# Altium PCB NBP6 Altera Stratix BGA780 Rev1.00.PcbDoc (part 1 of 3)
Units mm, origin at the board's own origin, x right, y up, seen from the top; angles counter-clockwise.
Board outline 69 x 80.99 mm, 6 copper layers (Top Layer, Upper, lower, VCC_PLANE, GND_PLANE, Bottom Layer); 92 components, 279 nets, 1271 pads, 560 vias.
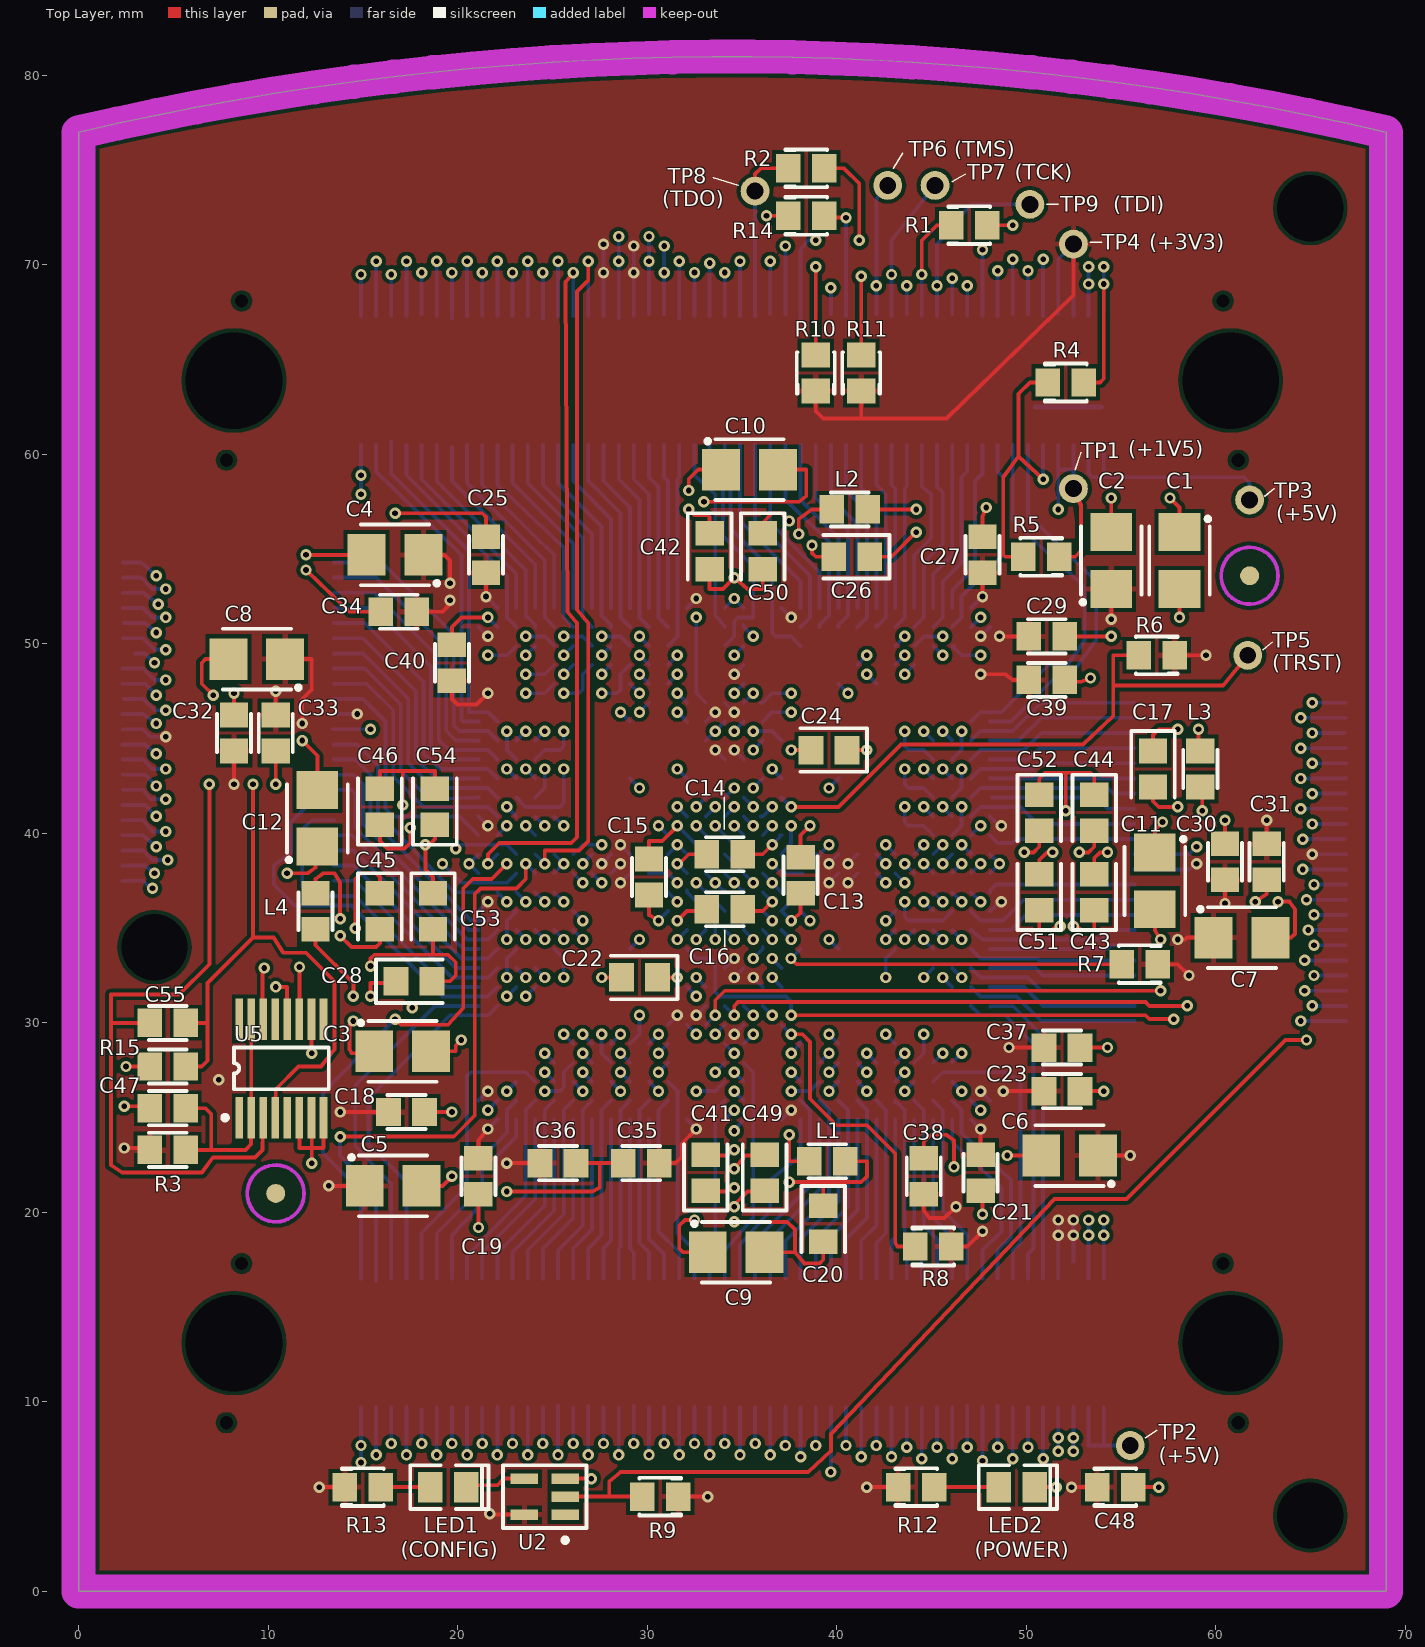
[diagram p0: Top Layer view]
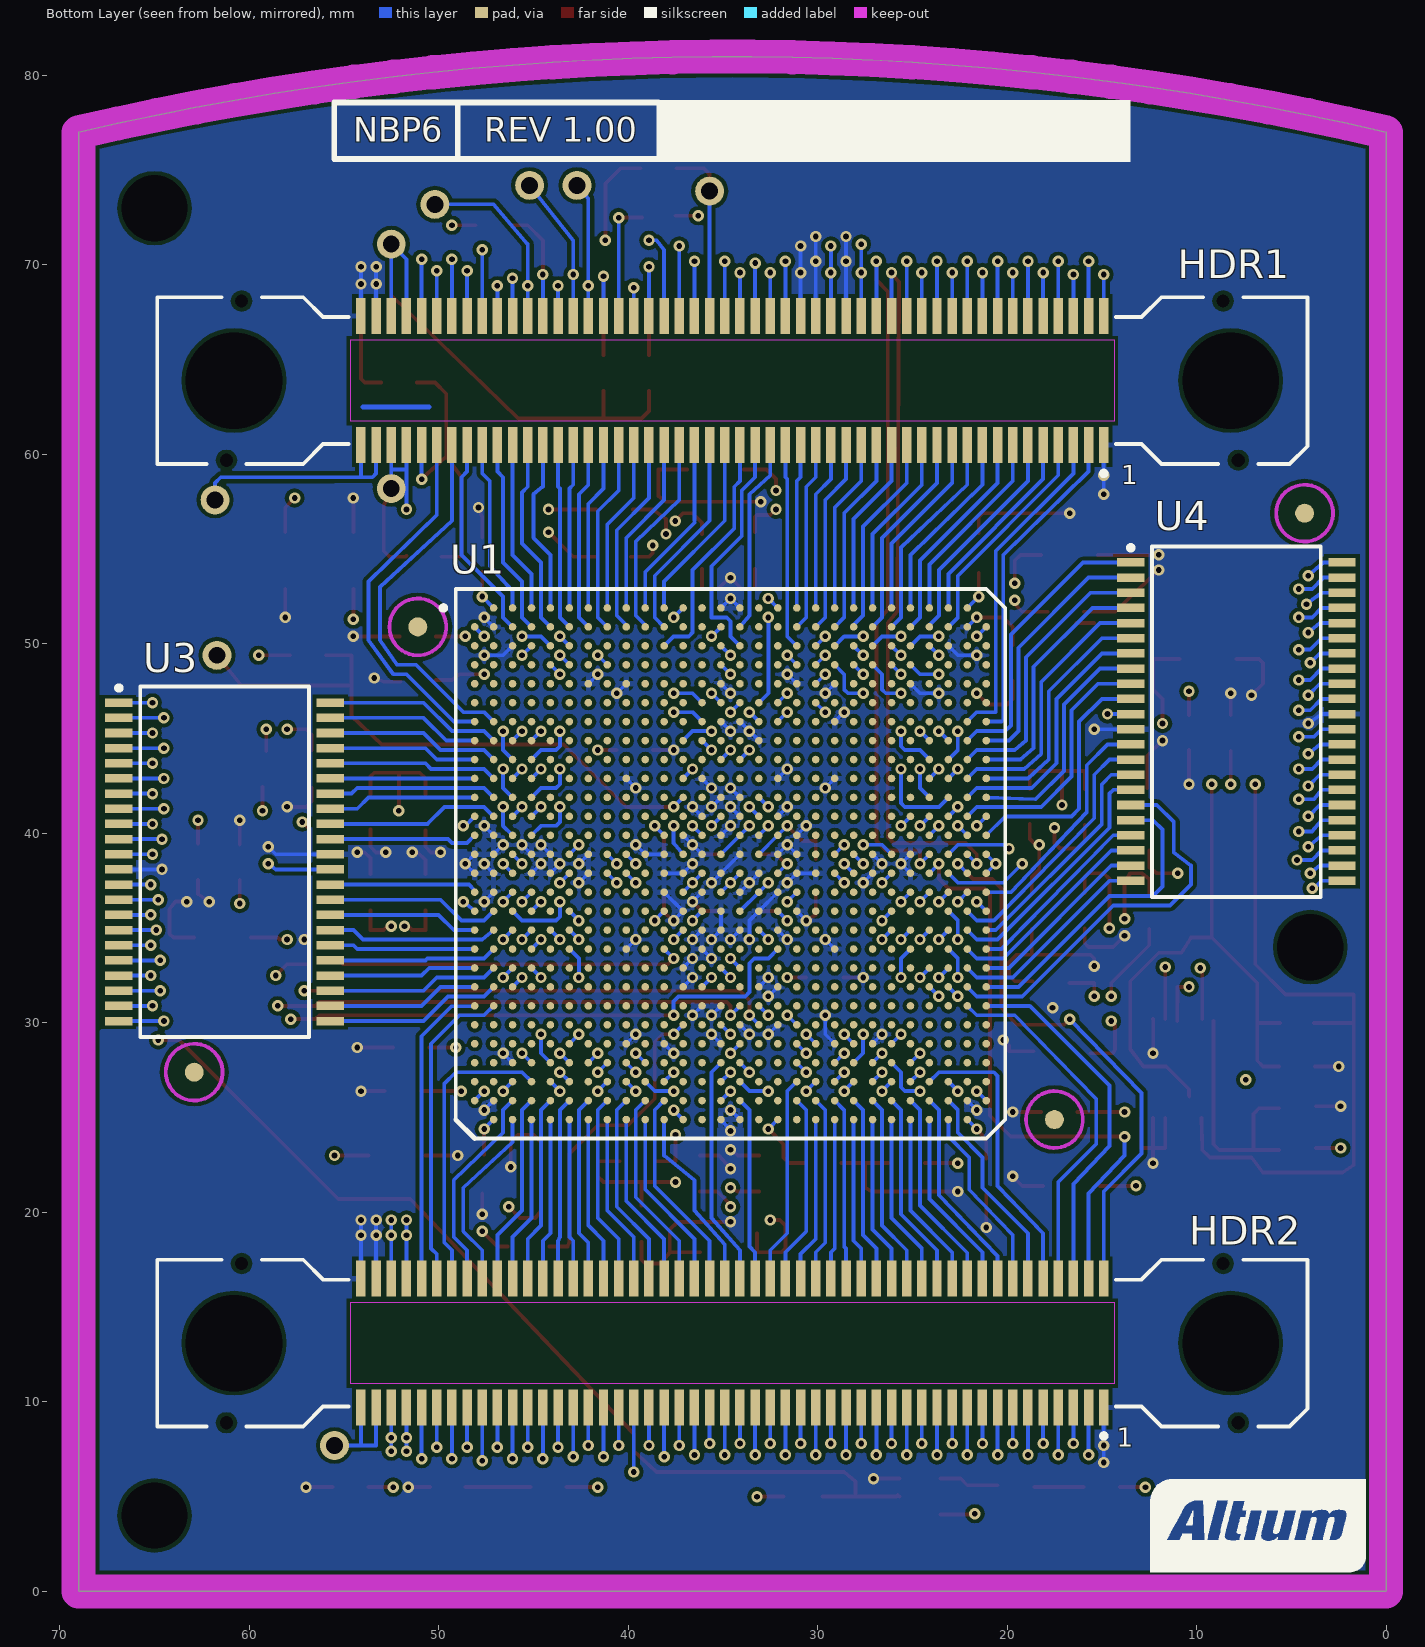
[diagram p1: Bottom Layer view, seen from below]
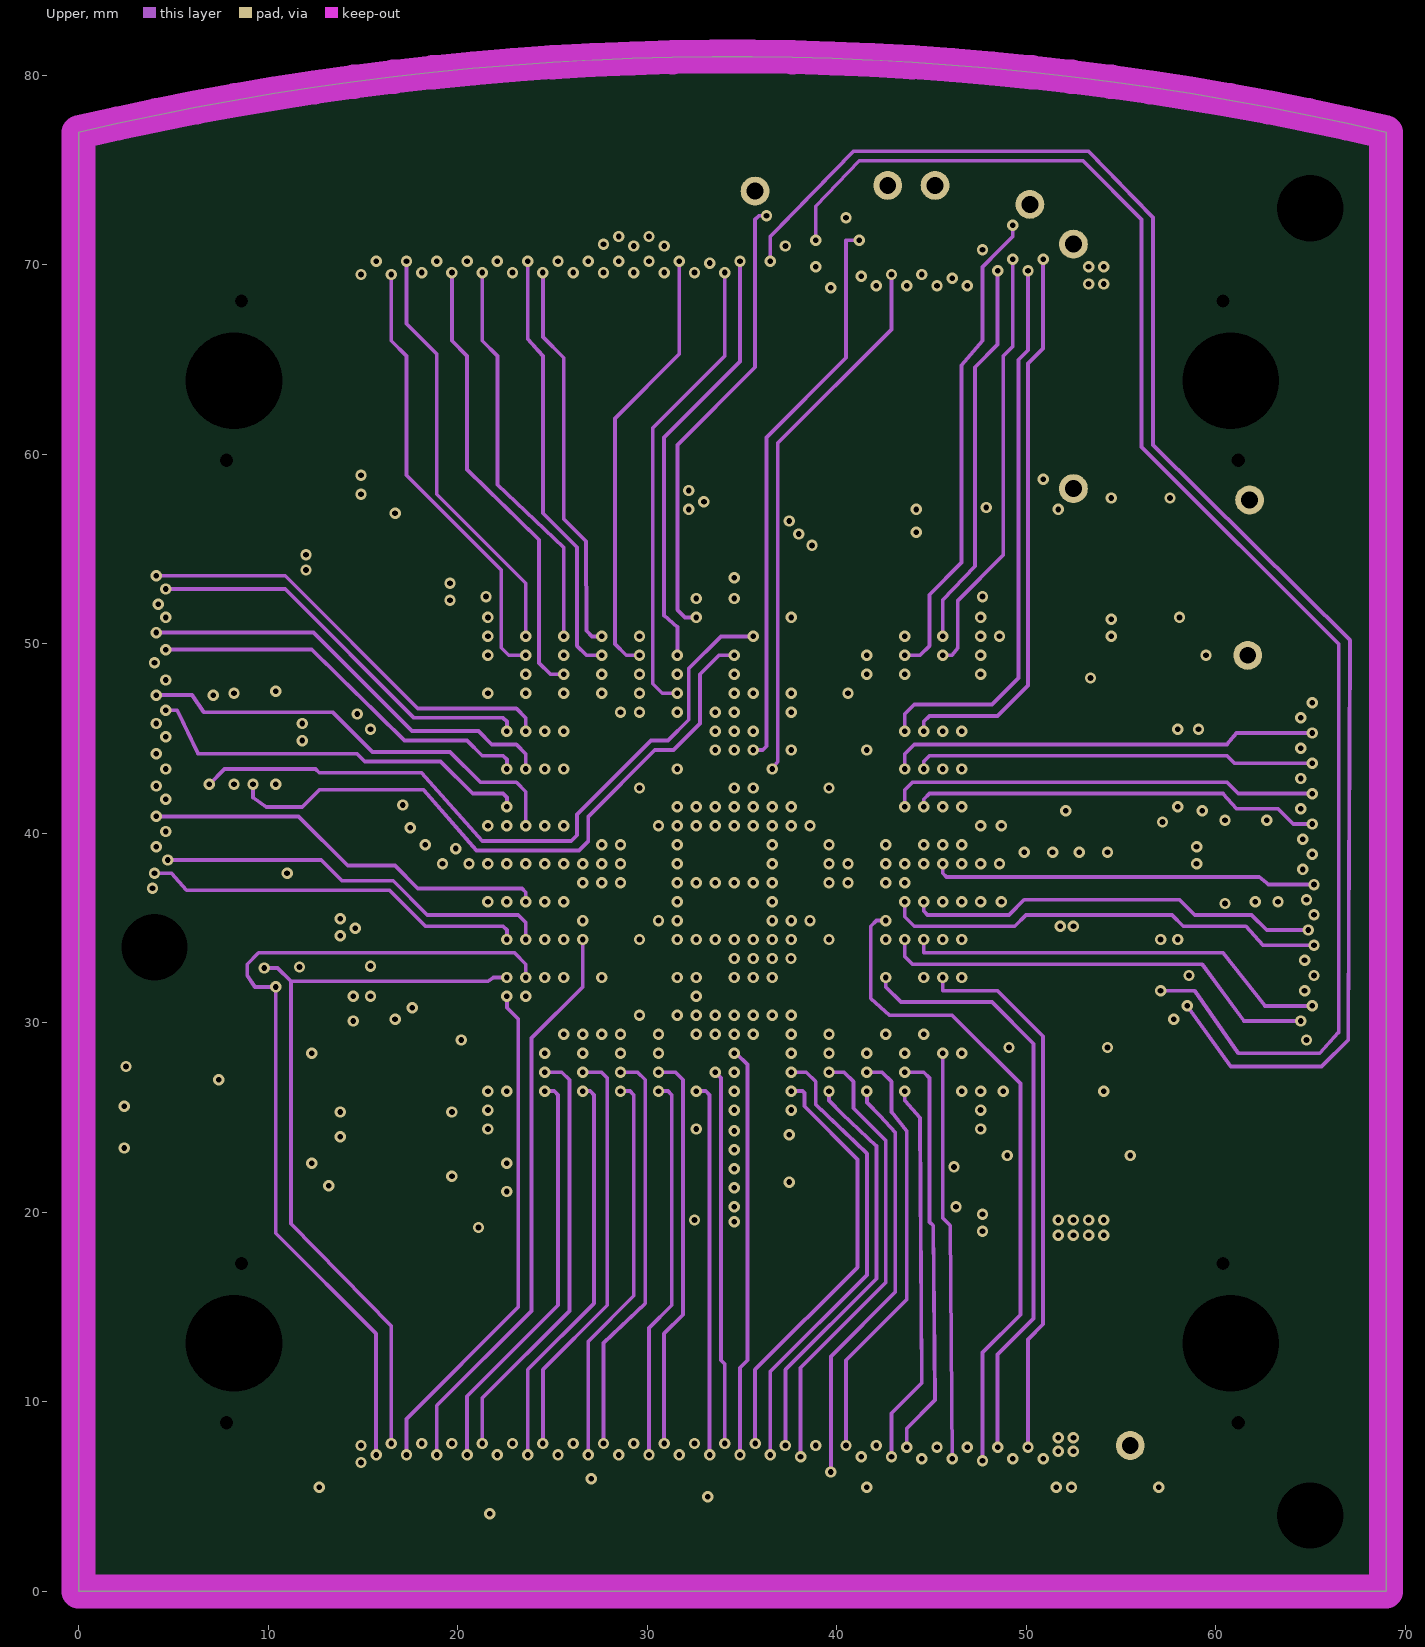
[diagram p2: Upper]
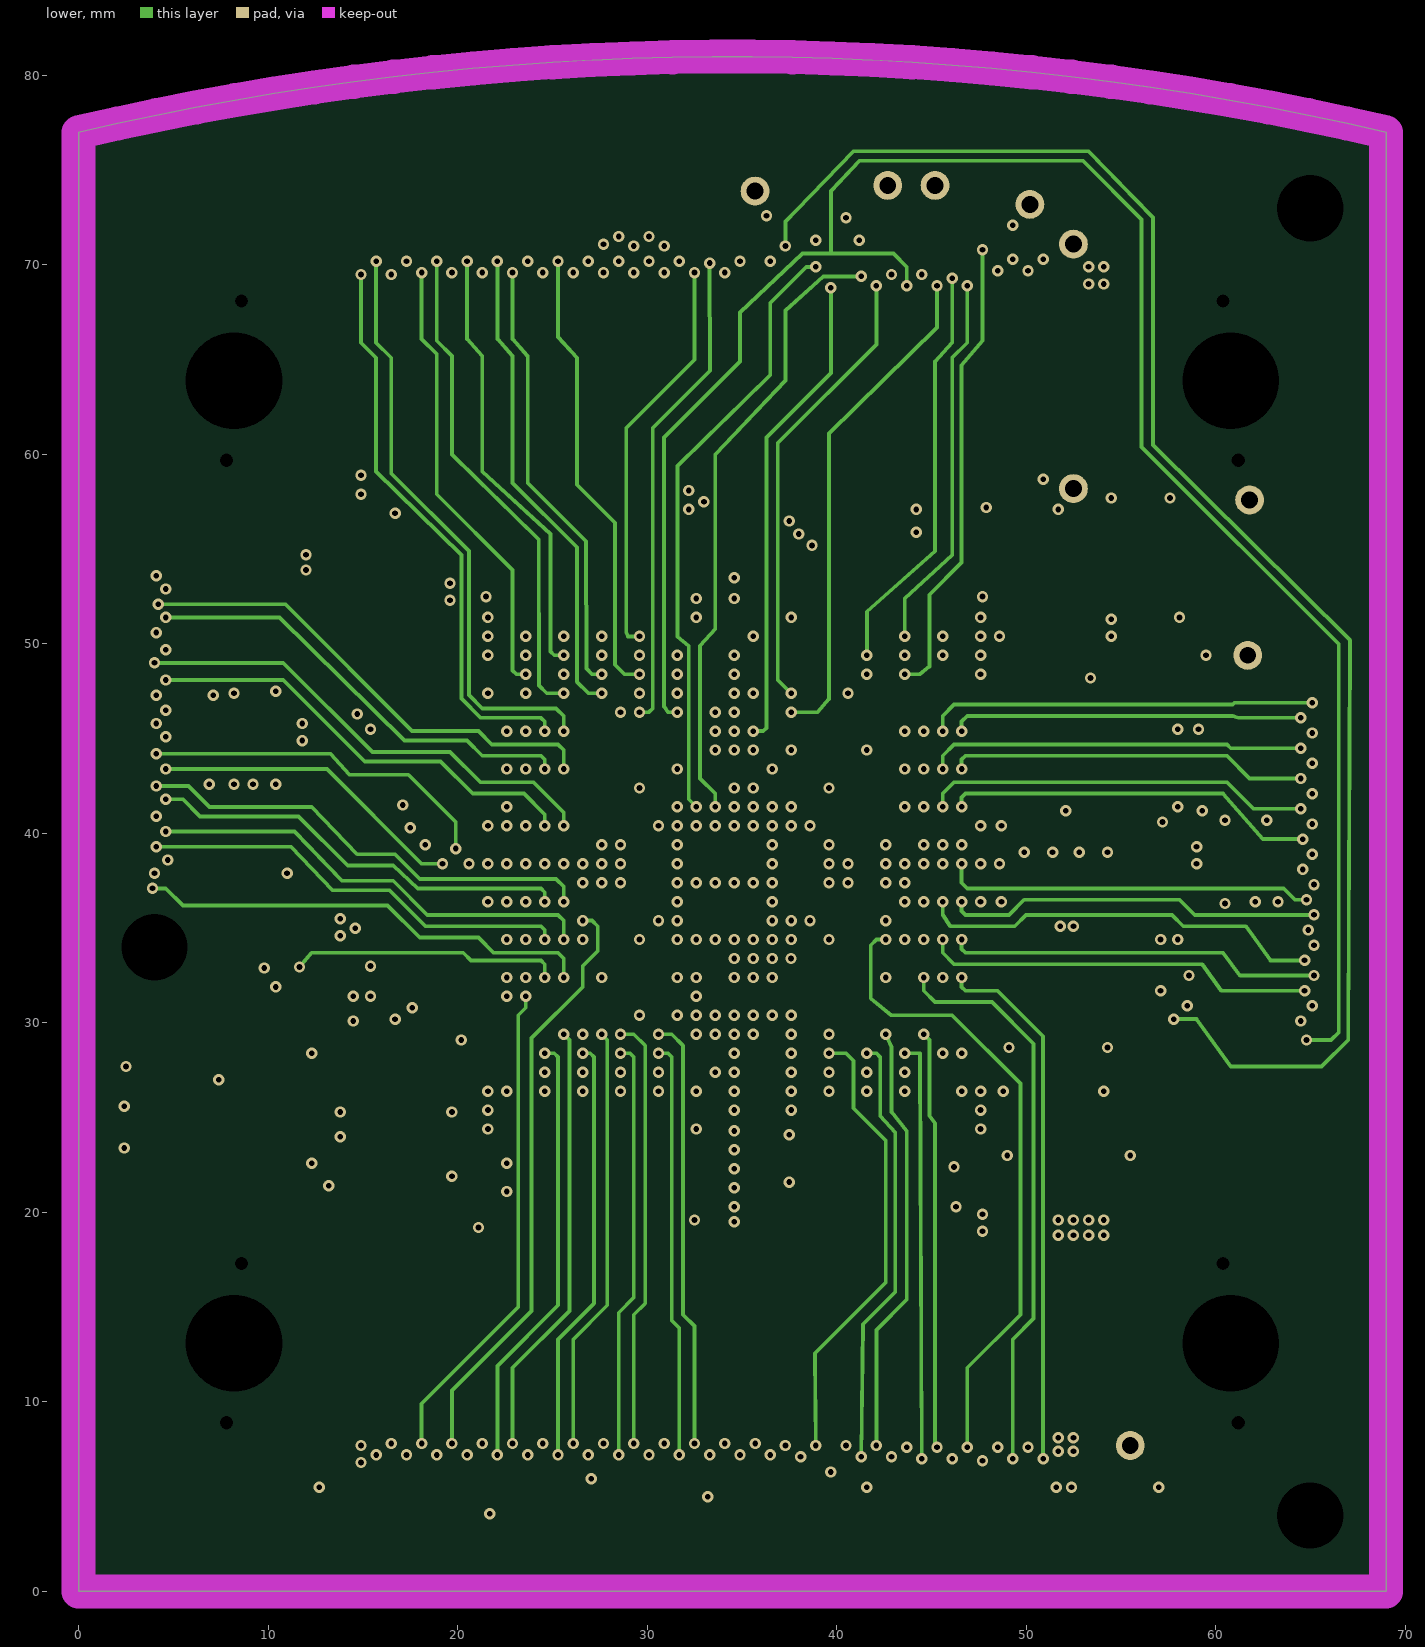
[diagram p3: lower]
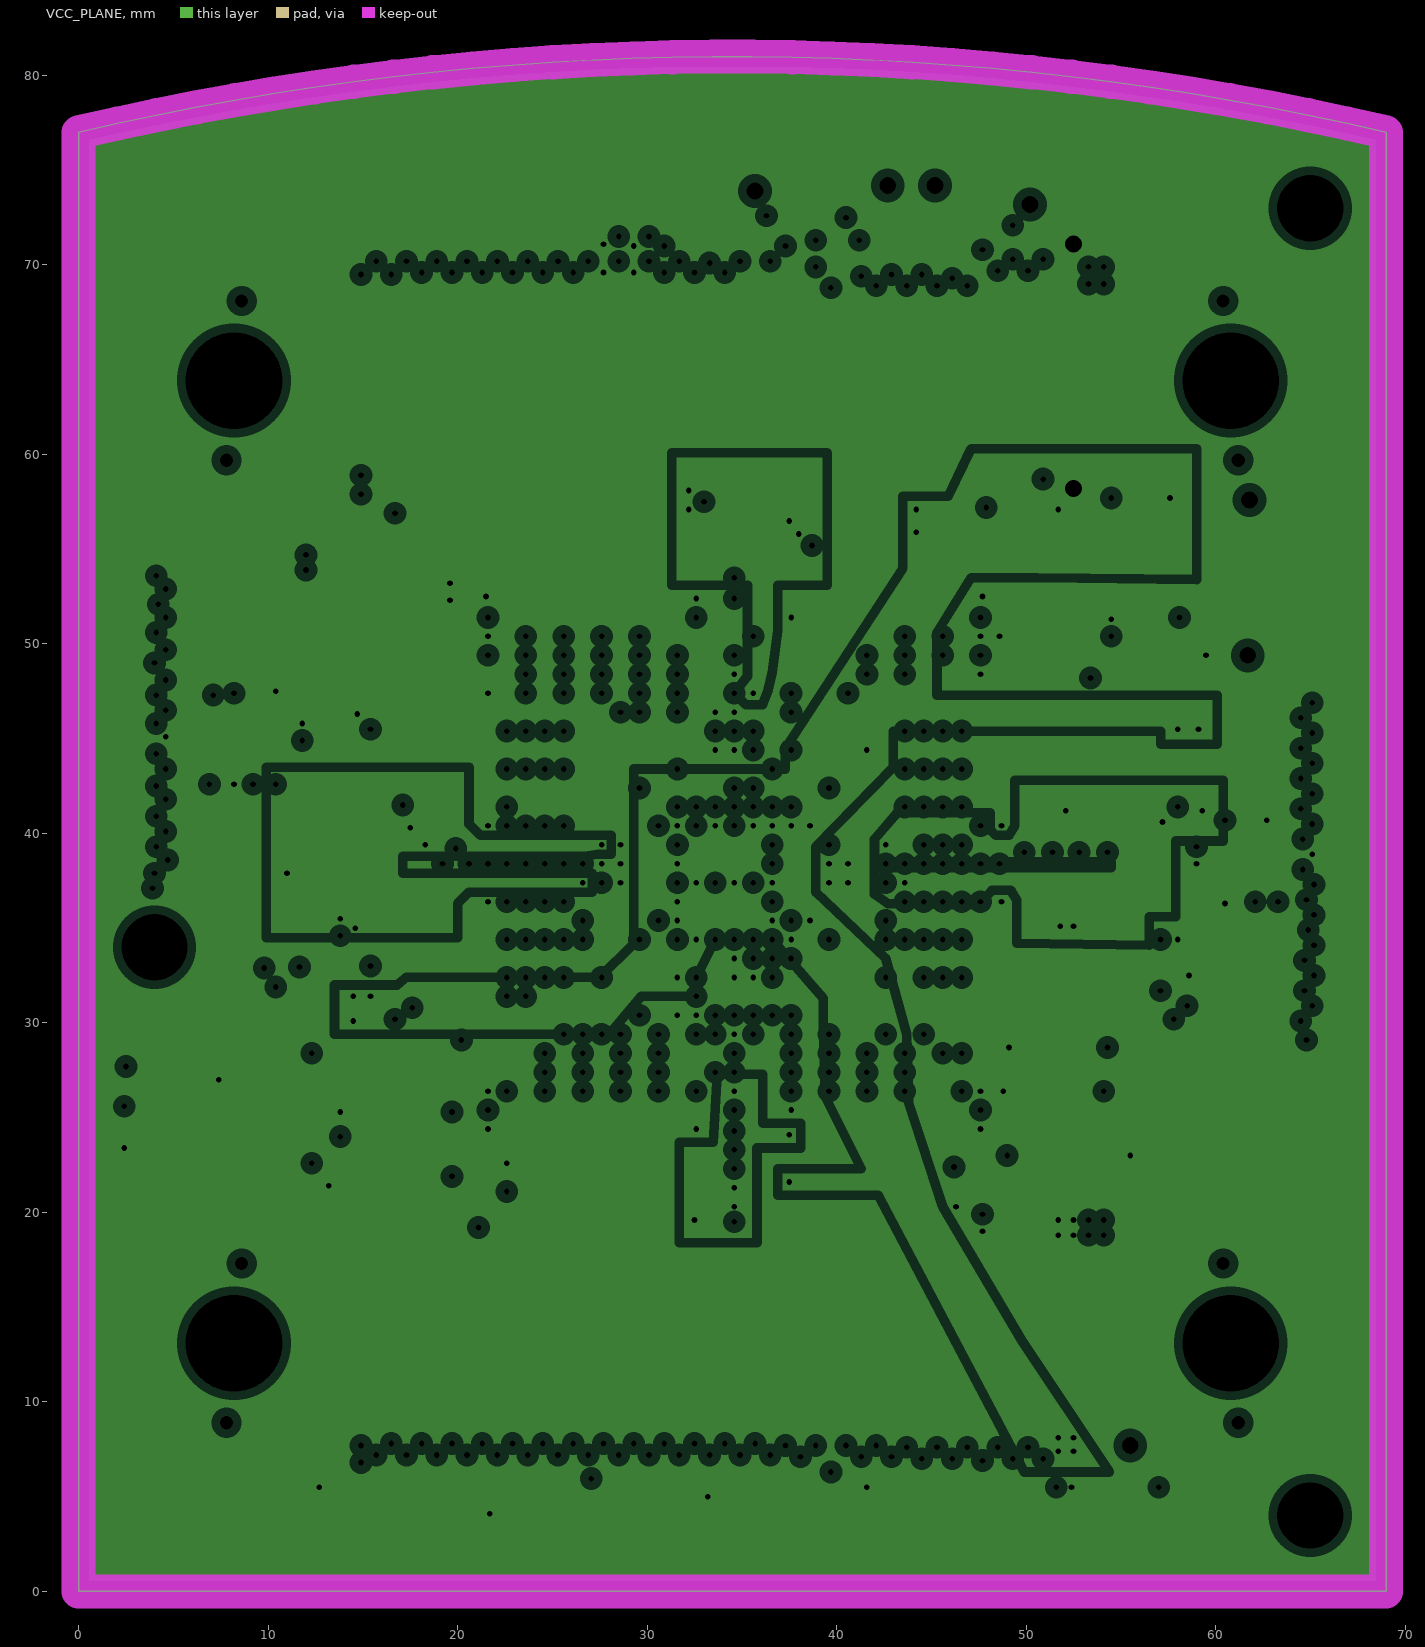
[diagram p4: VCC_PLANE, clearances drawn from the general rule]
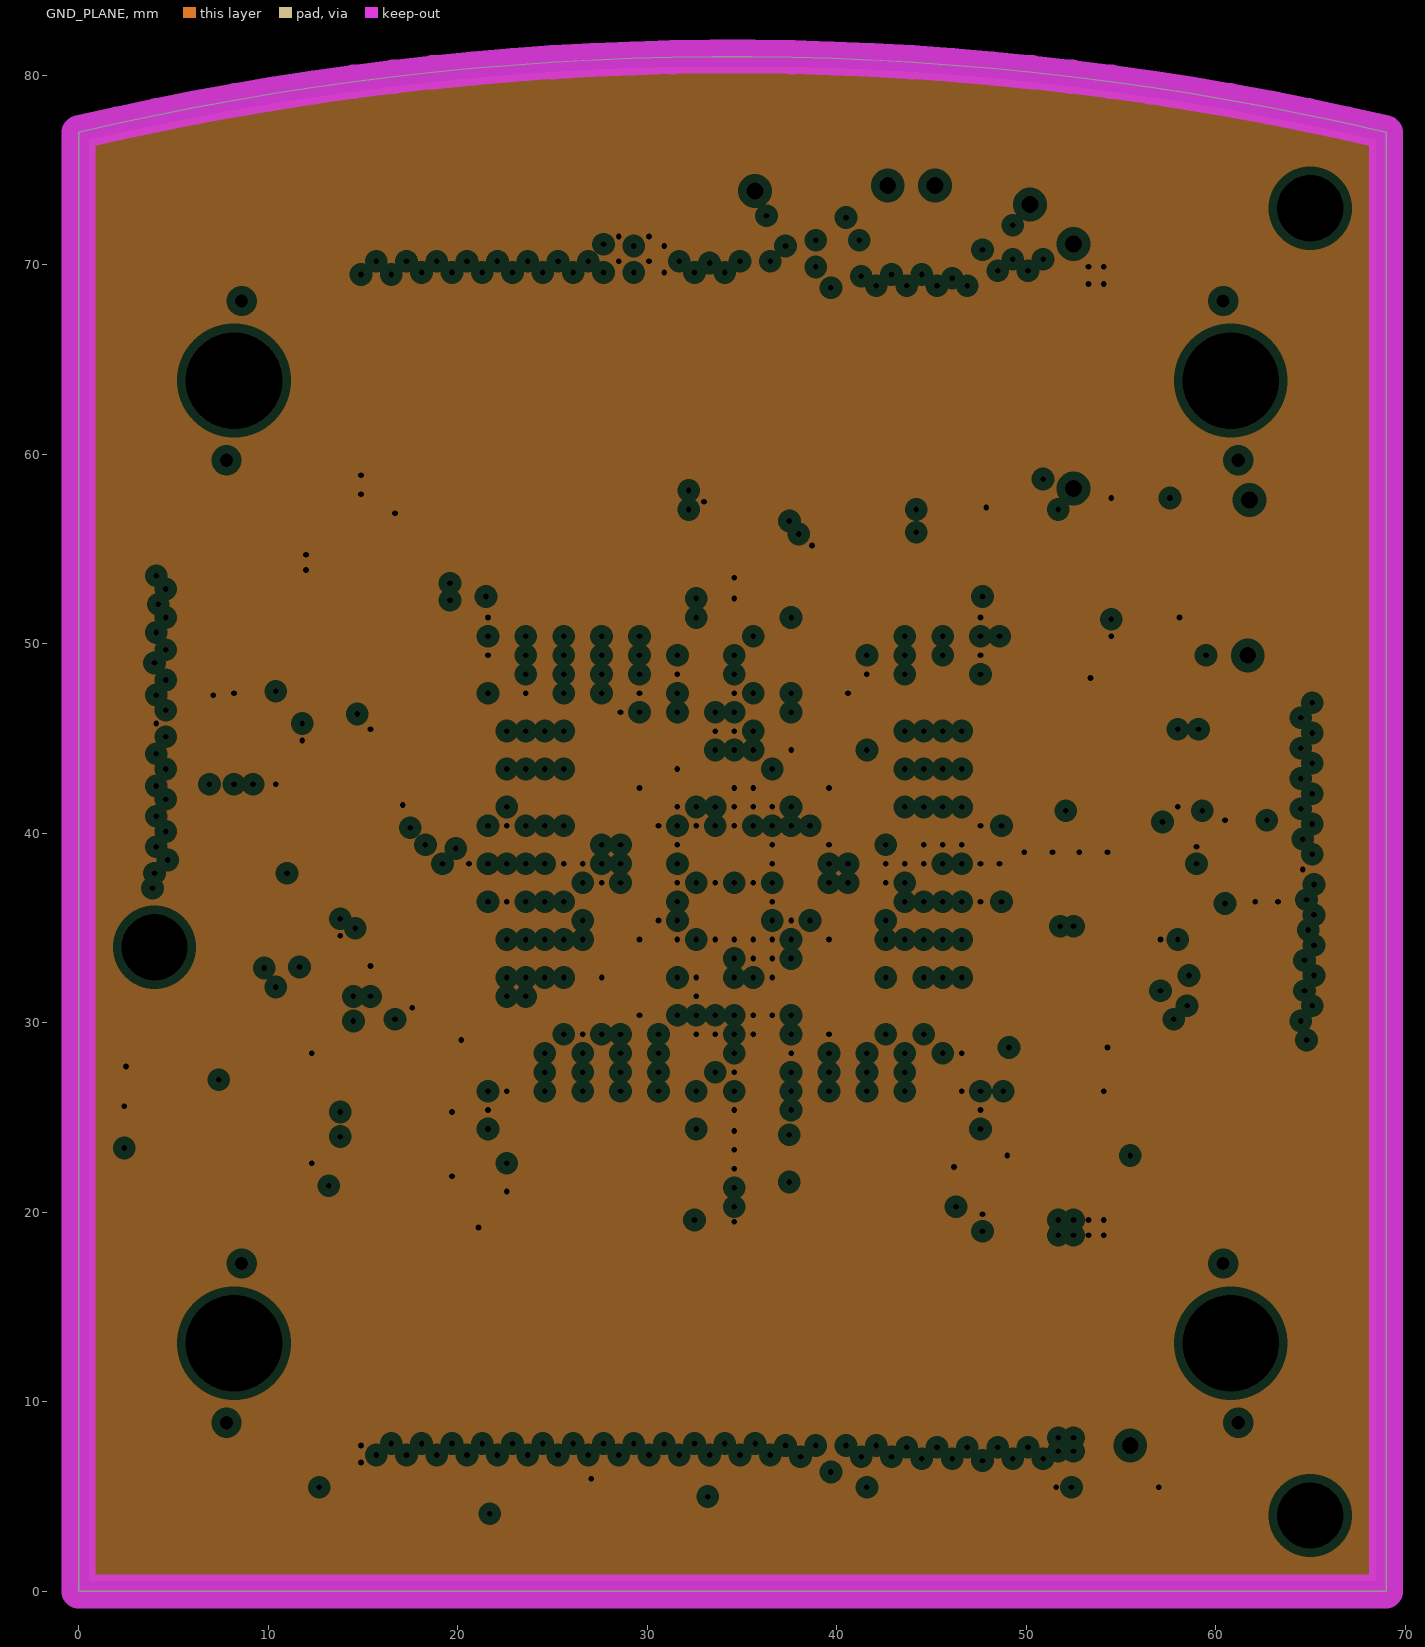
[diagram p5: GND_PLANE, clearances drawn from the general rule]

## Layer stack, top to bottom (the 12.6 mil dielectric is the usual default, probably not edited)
Top Layer: signal copper 0.0356
Dielectric: core 0.32, FR-4, Dk 4.8
Upper: signal copper 0.0356
Dielectric: prepreg 0.32, FR-4, Dk 4.8
lower: signal copper 0.0356
Dielectric: core 0.32, FR-4, Dk 4.8
VCC_PLANE: plane copper 0.0356, net (Multiple Nets)
Dielectric: prepreg 0.32, FR-4, Dk 4.8
GND_PLANE: plane copper 0.0356, net GND
Dielectric: core 0.32, FR-4, Dk 4.8
Bottom Layer: signal copper 0.0356

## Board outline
0,0 0.001,77 cw(c34.5,-69.801) 69,77 69,0

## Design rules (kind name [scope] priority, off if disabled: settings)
Clearance Clearance_Polygons [InPolygon] p1: gap=0.2
ComponentClearance [All] p1: gap=0.2 collisioncheckmode=3 verticalgap=0.254 showdistances=FALSE
FabricationTestPointUsage TestPointUsage [All] p1 off: valid=0 allowmultiple=FALSE
FabricationTestpoint Testpoint [All] p1 off: side=3 testpointundercomponent=TRUE minsize=1.016 maxsize=2.54 preferedsize=1.524 minholesize=0 maxholesize=1.016 preferedholesize=0.813 testpointgrid=0.025 allowsidetop=TRUE allowsidebottom=TRUE usegrid=TRUE gridtolerance=0
HoleSize [All] p1: absolutevalues=TRUE maxlimit=5.2 minlimit=0.25 maxpercent=80.000 minpercent=20.000
PlaneClearance [All] p1: clearance=0.45
PlaneConnect [All] p1: planeconnectstyle=Direct reliefexpansion=0.5 reliefentries=4 reliefconductorwidth=0.25 reliefairgap=0.25
PolygonConnect [All] p1: connectstyle=Relief reliefconductorwidth=0.3 reliefentries=4 polygonreliefangle="90 Angle"
RoutingVias [All] p1: holewidth=0.3 width=0.6 viastyle="Through Hole" minholewidth=0.3 minwidth=0.6 maxholewidth=0.5 maxwidth=1.4
SMDNeckDown [All] p1: percent=100.000
SilkscreenOverComponentPads [All] p1: minsilkscreentomaskgap=0.254
SolderMaskExpansion SolderMaskExpansion_Vias [IsVia] p1: expansion=-0.4
SolderMaskExpansion [All] p2: expansion=0.1
Width [All] p1: maxlimit=1.4 minlimit=0.2 preferedwidth=0.2
21 further rules are at their usual default settings.

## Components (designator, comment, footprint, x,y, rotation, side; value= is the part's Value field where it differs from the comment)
C1 "10uF" MCCT-B 58.1,54.4 r270 top
C2 "10uF" MCCT-B 54.5,54.4 r90 top
C3 "10uF" MCCT-B 17.1,28.5 r0 top
C4 "10uF" MCCT-B 16.7,54.7 r180 top
C5 "10uF" MCCT-B 16.6,21.4 r0 top
C6 "10uF" MCCT-B 52.3,23 r180 top
C7 "10uF" MCCT-B 61.4,34.5 r0 top
C8 "10uF" MCCT-B 9.4,49.2 r180 top
C9 "10uF" MCCT-B 34.7,17.9 r0 top
C10 "10uF" MCCT-B 35.4,59.2 r0 top
C11 "10uF" MCCT-B 56.8,37.5 r270 top
C12 "10uF" MCCT-B 12.6,40.8 r90 top
C13 "0.1uF" CC2012-0805 38.1,37.8 r270 top locked
C14 "0.1uF" CC2012-0805 34.1,38.9 r0 top locked
C15 "0.1uF" CC2012-0805 30.1,37.7 r270 top locked
C16 "0.1uF" CC2012-0805 34.1,36 r0 top
C17 "0.1uF" CC2012-0805 56.7,43.4 r270 top
C18 "0.1uF" CC2012-0805 17.3,25.3 r0 top
C19 "0.1uF" CC2012-0805 21.1,21.9 r270 top
C20 "0.1uF" CC2012-0805 39.3,19.4 r270 top
C21 "0.1uF" CC2012-0805 47.6,22.1 r270 top
C22 "0.1uF" CC2012-0805 29.6,32.4 r180 top
C23 "0.1uF" CC2012-0805 51.9,26.4 r0 top
C24 "0.1uF" CC2012-0805 39.6,44.4 r180 top
C25 "0.1uF" CC2012-0805 21.5,54.7 r90 top
C26 "0.1uF" CC2012-0805 40.8,54.6 r180 top
C27 "0.1uF" CC2012-0805 47.7,54.7 r90 top
C28 "0.1uF" CC2012-0805 17.7,32.2 r0 top
C29 "0.1uF" CC2012-0805 51.1,50.4 r0 top
C30 "0.1uF" CC2012-0805 60.5,38.5 r90 top
C31 "0.1uF" CC2012-0805 62.7,38.5 r270 top
C32 "0.1uF" CC2012-0805 8.2,45.3 r90 top
C33 "0.1uF" CC2012-0805 10.4,45.3 r270 top
C34 "0.1uF" CC2012-0805 16.9,51.7 r180 top
C35 "0.1uF" CC2012-0805 29.7,22.6 r180 top
C36 "0.1uF" CC2012-0805 25.3,22.6 r0 top
C37 "0.1uF" CC2012-0805 51.9,28.7 r0 top
C38 "0.1uF" CC2012-0805 44.6,21.9 r90 top
C39 "0.1uF" CC2012-0805 51.1,48.1 r0 top
C40 "0.1uF" CC2012-0805 19.7,49 r90 top
C41 "0.1uF" CC2012-0805 33.1,22.1 r90 top
C42 "0.1uF" CC2012-0805 33.3,54.9 r270 top
C43 "0.1uF" CC2012-0805 53.6,36.9 r90 top
C44 "0.1uF" CC2012-0805 53.6,41.1 r270 top
C45 "0.1uF" CC2012-0805 15.9,35.9 r270 top
C46 "0.1uF" CC2012-0805 15.9,41.4 r90 top
C47 "0.1uF" CC2012-0805 4.7,25.5 r180 top
C48 "0.1uF" CC2012-0805 54.7,5.5 r0 top
C49 "0.001uF" CC2012-0805 36.2,22.1 r90 top
C50 "0.001uF" CC2012-0805 36.1,54.9 r270 top
C51 "0.001uF" CC2012-0805 50.7,36.9 r90 top
C52 "0.001uF" CC2012-0805 50.7,41.1 r270 top
C53 "0.001uF" CC2012-0805 18.7,35.9 r270 top
C54 "0.001uF" CC2012-0805 18.8,41.4 r90 top
C55 "10nF" CC2012-0805 4.7,30 r180 top
HDR1 "54075-1009-HD1" 54075 34.5,63.9 r0 bottom locked
HDR2 "54075-1009-HD2" 54075 34.5,13.1 r0 bottom locked
L1 "Ferrite Bead 50Mhz" CC2012-0805 39.5,22.7 r180 top
L2 "Ferrite Bead 50Mhz" CC2012-0805 40.7,57.1 r180 top
L3 "Ferrite Bead 50Mhz" CC2012-0805 59.2,43.4 r270 top
L4 "Ferrite Bead 50Mhz" CC2012-0805 12.5,35.9 r90 top
LED1 "HSMG-C170" "SMD _LED" 19.5,5.5 r180 top locked
LED2 "HSMH-C170" "SMD _LED" 49.5,5.5 r180 top locked
R1 "100R" CC2012-0805 47,72.1 r0 top
R2 "100R" CC2012-0805 38.4,75.1 r0 top
R3 "100R" CC2012-0805 4.7,23.3 r0 top
R4 "47R" CC2012-0805 52.1,63.8 r0 top
R5 "DO NOT INSTALL" CC2012-0805 50.8,54.6 r180 top
R6 "4K7" CC2012-0805 56.9,49.4 r180 top
R7 "4K7" CC2012-0805 56,33.1 r180 top
R8 "4K7" CC2012-0805 45.1,18.2 r0 top
R9 "4K7" CC2012-0805 30.7,5 r180 top
R10 "4K7" CC2012-0805 38.9,64.3 r90 top
R11 "4K7" CC2012-0805 41.3,64.3 r90 top
R12 "270R" CC2012-0805 44.2,5.5 r0 top
R13 "270R" CC2012-0805 15,5.5 r0 top
R14 "33R" CC2012-0805 38.4,72.6 r0 top
R15 "1M" CC2012-0805 4.7,27.7 r0 top
TP1 "TestPin" TestPin 52.5,58.2 r90 top
TP2 "TestPin" TestPin 55.5,7.7 r90 top
TP3 "TestPin" TestPin 61.8,57.6 r90 top
TP4 "TestPin" TestPin 52.5,71.1 r90 top
TP5 "TestPin" TestPin 61.7,49.4 r90 top
TP6 "TestPin" TestPin 42.7,74.2 r90 top
TP7 "TestPin" TestPin 45.2,74.2 r90 top
TP8 "TestPin" TestPin 35.7,73.9 r90 top
TP9 "TestPin" TestPin 50.2,73.2 r90 top
U1 "EP1S10F780I7" FBGA780 34.6,38.4 r180 bottom locked
U2 "SN74LVC1G04DBV" SO-G5/P.95 24.6,5 r90 top
U3 "SRAM 512Kx16 TSOP44" SO-G44/P.8 61.3,38.5 r270 bottom locked
U4 "SRAM 512Kx16 TSOP44" SO-G44/P.8 7.9,45.9 r270 bottom locked
U5 "MAX1617DBR2" QSOP16 10.7,27.6 r0 top

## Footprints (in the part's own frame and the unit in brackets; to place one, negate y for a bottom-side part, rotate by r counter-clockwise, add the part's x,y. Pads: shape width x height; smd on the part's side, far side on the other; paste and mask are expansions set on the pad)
54075 [mm] "Connector; Docking Station, Receptacle; 100 Position; Vertical"
  rect 0.5x1.9 smd: 1(-19.6,3.4) 2(-19.6,-3.4) 3(-18.8,3.4) 4(-18.8,-3.4) 5(-18,3.4) 6(-18,-3.4) 7(-17.2,3.4) 8(-17.2,-3.4) 9(-16.4,3.4) 10(-16.4,-3.4) 11(-15.6,3.4) 12(-15.6,-3.4) 13(-14.8,3.4) 14(-14.8,-3.4) 15(-14,3.4) 16(-14,-3.4) 17(-13.2,3.4) 18(-13.2,-3.4) 19(-12.4,3.4) 20(-12.4,-3.4) 21(-11.6,3.4) 22(-11.6,-3.4) 23(-10.8,3.4) 24(-10.8,-3.4) 25(-10,3.4) 26(-10,-3.4) 27(-9.2,3.4) 28(-9.2,-3.4) 29(-8.4,3.4) 30(-8.4,-3.4) 31(-7.6,3.4) 32(-7.6,-3.4) 33(-6.8,3.4) 34(-6.8,-3.4) 35(-6,3.4) 36(-6,-3.4) 37(-5.2,3.4) 38(-5.2,-3.4) 39(-4.4,3.4) 40(-4.4,-3.4) 41(-3.6,3.4) 42(-3.6,-3.4) 43(-2.8,3.4) 44(-2.8,-3.4) 45(-2,3.4) 46(-2,-3.4) 47(-1.2,3.4) 48(-1.2,-3.4) 49(-0.4,3.4) 50(-0.4,-3.4) 51(0.4,3.4) 52(0.4,-3.4) 53(1.2,3.4) 54(1.2,-3.4) 55(2,3.4) 56(2,-3.4) 57(2.8,3.4) 58(2.8,-3.4) 59(3.6,3.4) 60(3.6,-3.4) 61(4.4,3.4) 62(4.4,-3.4) 63(5.2,3.4) 64(5.2,-3.4) 65(6,3.4) 66(6,-3.4) 67(6.8,3.4) 68(6.8,-3.4) 69(7.6,3.4) 70(7.6,-3.4) 71(8.4,3.4) 72(8.4,-3.4) 73(9.2,3.4) 74(9.2,-3.4) 75(10,3.4) 76(10,-3.4) 77(10.8,3.4) 78(10.8,-3.4) 79(11.6,3.4) 80(11.6,-3.4) 81(12.4,3.4) 82(12.4,-3.4) 83(13.2,3.4) 84(13.2,-3.4) 85(14,3.4) 86(14,-3.4) 87(14.8,3.4) 88(14.8,-3.4) 89(15.6,3.4) 90(15.6,-3.4) 91(16.4,3.4) 92(16.4,-3.4) 93(17.2,3.4) 94(17.2,-3.4) 95(18,3.4) 96(18,-3.4) 97(18.8,3.4) 98(18.8,-3.4) 99(19.6,3.4) 100(19.6,-3.4)
  round 0.5 hole 0.7 unplated: MH1(-26.7,4.2) MH2(-25.9,-4.2) MH3(26.7,4.2) MH4(25.9,-4.2)
  round 4.8 hole 5.1 unplated: MH5(-26.3,0) MH6(26.3,0)
  Top Layer keep-out region: -20.15,2.15 20.15,2.15 20.15,-2.15 -20.15,-2.15
  silkscreen extent -30.35,-4.4 30.35,5.02
CC2012-0805 [mm]
  rect 1.3x1.5 smd: 1(-0.95,0) 2(0.95,0)
  silkscreen extent -1,-0.9 1,0.9
FBGA780 [mm] "780-Pin Thermally Enhanced FineLine Ball-Grid Array (FBGA)"
  round 0.4 smd: A2(-12.5,13.5) A3(-11.5,13.5) A4(-10.5,13.5) A5(-9.5,13.5) A6(-8.5,13.5) A7(-7.5,13.5) A8(-6.5,13.5) A9(-5.5,13.5) A10(-4.5,13.5) A11(-3.5,13.5) A12(-2.5,13.5) A13(-1.5,13.5) A14(-0.5,13.5) A15(0.5,13.5) A16(1.5,13.5) A17(2.5,13.5) A18(3.5,13.5) A19(4.5,13.5) A20(5.5,13.5) A21(6.5,13.5) A22(7.5,13.5) A23(8.5,13.5) A24(9.5,13.5) A25(10.5,13.5) A26(11.5,13.5) A27(12.5,13.5) AA1(-13.5,-6.5) AA2(-12.5,-6.5) AA3(-11.5,-6.5) AA4(-10.5,-6.5) AA5(-9.5,-6.5) AA6(-8.5,-6.5) AA7(-7.5,-6.5) AA8(-6.5,-6.5) AA9(-5.5,-6.5) AA10(-4.5,-6.5) AA11(-3.5,-6.5) AA12(-2.5,-6.5) AA13(-1.5,-6.5) AA14(-0.5,-6.5) AA15(0.5,-6.5) AA16(1.5,-6.5) AA17(2.5,-6.5) AA18(3.5,-6.5) AA19(4.5,-6.5) AA20(5.5,-6.5) AA21(6.5,-6.5) AA22(7.5,-6.5) AA23(8.5,-6.5) AA24(9.5,-6.5) AA25(10.5,-6.5) AA26(11.5,-6.5) AA27(12.5,-6.5) AA28(13.5,-6.5) AB1(-13.5,-7.5) AB2(-12.5,-7.5) AB3(-11.5,-7.5) AB4(-10.5,-7.5) AB5(-9.5,-7.5) AB6(-8.5,-7.5) AB7(-7.5,-7.5) AB8(-6.5,-7.5) AB9(-5.5,-7.5) AB10(-4.5,-7.5) AB11(-3.5,-7.5) AB12(-2.5,-7.5) AB13(-1.5,-7.5) AB14(-0.5,-7.5) AB15(0.5,-7.5) AB16(1.5,-7.5) AB17(2.5,-7.5) AB18(3.5,-7.5) AB19(4.5,-7.5) AB20(5.5,-7.5) AB21(6.5,-7.5) AB22(7.5,-7.5) AB23(8.5,-7.5) AB24(9.5,-7.5) AB25(10.5,-7.5) AB26(11.5,-7.5) AB27(12.5,-7.5) AB28(13.5,-7.5) AC1(-13.5,-8.5) AC2(-12.5,-8.5) AC3(-11.5,-8.5) AC4(-10.5,-8.5) AC5(-9.5,-8.5) AC6(-8.5,-8.5) AC7(-7.5,-8.5) AC8(-6.5,-8.5) AC9(-5.5,-8.5) AC10(-4.5,-8.5) AC11(-3.5,-8.5) AC12(-2.5,-8.5) AC13(-1.5,-8.5) AC14(-0.5,-8.5) AC15(0.5,-8.5) AC16(1.5,-8.5) AC17(2.5,-8.5) AC18(3.5,-8.5) AC19(4.5,-8.5) AC20(5.5,-8.5) AC21(6.5,-8.5) AC22(7.5,-8.5) AC23(8.5,-8.5) AC24(9.5,-8.5) AC25(10.5,-8.5) AC26(11.5,-8.5) AC27(12.5,-8.5) AC28(13.5,-8.5) AD1(-13.5,-9.5) AD2(-12.5,-9.5) AD3(-11.5,-9.5) AD4(-10.5,-9.5) AD5(-9.5,-9.5) AD6(-8.5,-9.5) AD7(-7.5,-9.5) AD8(-6.5,-9.5) AD9(-5.5,-9.5) AD10(-4.5,-9.5) AD11(-3.5,-9.5) AD12(-2.5,-9.5) AD13(-1.5,-9.5) AD14(-0.5,-9.5) AD15(0.5,-9.5) AD16(1.5,-9.5) AD17(2.5,-9.5) AD18(3.5,-9.5) AD19(4.5,-9.5) AD20(5.5,-9.5) AD21(6.5,-9.5) AD22(7.5,-9.5) AD23(8.5,-9.5) AD24(9.5,-9.5) AD25(10.5,-9.5) AD26(11.5,-9.5) AD27(12.5,-9.5) AD28(13.5,-9.5) AE1(-13.5,-10.5) AE2(-12.5,-10.5) AE3(-11.5,-10.5) AE4(-10.5,-10.5) AE5(-9.5,-10.5) AE6(-8.5,-10.5) AE7(-7.5,-10.5) AE8(-6.5,-10.5) AE9(-5.5,-10.5) AE10(-4.5,-10.5) AE11(-3.5,-10.5) AE12(-2.5,-10.5) AE13(-1.5,-10.5) AE14(-0.5,-10.5) AE15(0.5,-10.5) AE16(1.5,-10.5) AE17(2.5,-10.5) AE18(3.5,-10.5) AE19(4.5,-10.5) AE20(5.5,-10.5) AE21(6.5,-10.5) AE22(7.5,-10.5) AE23(8.5,-10.5) AE24(9.5,-10.5) AE25(10.5,-10.5) AE26(11.5,-10.5) AE27(12.5,-10.5) AE28(13.5,-10.5) AF1(-13.5,-11.5) AF2(-12.5,-11.5) AF3(-11.5,-11.5) AF4(-10.5,-11.5) AF5(-9.5,-11.5) AF6(-8.5,-11.5) AF7(-7.5,-11.5) AF8(-6.5,-11.5) AF9(-5.5,-11.5) AF10(-4.5,-11.5) AF11(-3.5,-11.5) AF12(-2.5,-11.5) AF13(-1.5,-11.5) AF14(-0.5,-11.5) AF15(0.5,-11.5) AF16(1.5,-11.5) AF17(2.5,-11.5) AF18(3.5,-11.5) AF19(4.5,-11.5) AF20(5.5,-11.5) AF21(6.5,-11.5) AF22(7.5,-11.5) AF23(8.5,-11.5) AF24(9.5,-11.5) AF25(10.5,-11.5) AF26(11.5,-11.5) AF27(12.5,-11.5) AF28(13.5,-11.5) AG1(-13.5,-12.5) AG2(-12.5,-12.5) AG3(-11.5,-12.5) AG4(-10.5,-12.5) AG5(-9.5,-12.5) AG6(-8.5,-12.5) AG7(-7.5,-12.5) AG8(-6.5,-12.5) AG9(-5.5,-12.5) AG10(-4.5,-12.5) AG11(-3.5,-12.5) AG12(-2.5,-12.5) AG13(-1.5,-12.5) AG14(-0.5,-12.5) AG15(0.5,-12.5) AG16(1.5,-12.5) AG17(2.5,-12.5) AG18(3.5,-12.5) AG19(4.5,-12.5) AG20(5.5,-12.5) AG21(6.5,-12.5) AG22(7.5,-12.5) AG23(8.5,-12.5) AG24(9.5,-12.5) AG25(10.5,-12.5) AG26(11.5,-12.5) AG27(12.5,-12.5) AG28(13.5,-12.5) AH2(-12.5,-13.5) AH3(-11.5,-13.5) AH4(-10.5,-13.5) AH5(-9.5,-13.5) AH6(-8.5,-13.5) AH7(-7.5,-13.5) AH8(-6.5,-13.5) AH9(-5.5,-13.5) AH10(-4.5,-13.5) AH11(-3.5,-13.5) AH12(-2.5,-13.5) AH13(-1.5,-13.5) AH14(-0.5,-13.5) AH15(0.5,-13.5) AH16(1.5,-13.5) AH17(2.5,-13.5) AH18(3.5,-13.5) AH19(4.5,-13.5) AH20(5.5,-13.5) AH21(6.5,-13.5) AH22(7.5,-13.5) AH23(8.5,-13.5) AH24(9.5,-13.5) AH25(10.5,-13.5) AH26(11.5,-13.5) AH27(12.5,-13.5) B1(-13.5,12.5) B2(-12.5,12.5) B3(-11.5,12.5) B4(-10.5,12.5) B5(-9.5,12.5) B6(-8.5,12.5) B7(-7.5,12.5) B8(-6.5,12.5) B9(-5.5,12.5) B10(-4.5,12.5) B11(-3.5,12.5) B12(-2.5,12.5) B13(-1.5,12.5) B14(-0.5,12.5) B15(0.5,12.5) B16(1.5,12.5) B17(2.5,12.5) B18(3.5,12.5) B19(4.5,12.5) B20(5.5,12.5) B21(6.5,12.5) B22(7.5,12.5) B23(8.5,12.5) B24(9.5,12.5) B25(10.5,12.5) B26(11.5,12.5) B27(12.5,12.5) B28(13.5,12.5) C1(-13.5,11.5) C2(-12.5,11.5) C3(-11.5,11.5) C4(-10.5,11.5) C5(-9.5,11.5) C6(-8.5,11.5) C7(-7.5,11.5) C8(-6.5,11.5) C9(-5.5,11.5) C10(-4.5,11.5) C11(-3.5,11.5) C12(-2.5,11.5) C13(-1.5,11.5) C14(-0.5,11.5) C15(0.5,11.5) C16(1.5,11.5) C17(2.5,11.5) C18(3.5,11.5) C19(4.5,11.5) C20(5.5,11.5) C21(6.5,11.5) C22(7.5,11.5) C23(8.5,11.5) C24(9.5,11.5) C25(10.5,11.5) C26(11.5,11.5) C27(12.5,11.5) C28(13.5,11.5) D1(-13.5,10.5) D2(-12.5,10.5) D3(-11.5,10.5) D4(-10.5,10.5) D5(-9.5,10.5) D6(-8.5,10.5) D7(-7.5,10.5) D8(-6.5,10.5) D9(-5.5,10.5) D10(-4.5,10.5) D11(-3.5,10.5) D12(-2.5,10.5) D13(-1.5,10.5) D14(-0.5,10.5) D15(0.5,10.5) D16(1.5,10.5) D17(2.5,10.5) D18(3.5,10.5) D19(4.5,10.5) D20(5.5,10.5) D21(6.5,10.5) D22(7.5,10.5) D23(8.5,10.5) D24(9.5,10.5) D25(10.5,10.5) D26(11.5,10.5) D27(12.5,10.5) D28(13.5,10.5) E1(-13.5,9.5) E2(-12.5,9.5) E3(-11.5,9.5) E4(-10.5,9.5) E5(-9.5,9.5) E6(-8.5,9.5) E7(-7.5,9.5) E8(-6.5,9.5) E9(-5.5,9.5) E10(-4.5,9.5) E11(-3.5,9.5) E12(-2.5,9.5) E13(-1.5,9.5) E14(-0.5,9.5) E15(0.5,9.5) E16(1.5,9.5) E17(2.5,9.5) E18(3.5,9.5) E19(4.5,9.5) E20(5.5,9.5) E21(6.5,9.5) E22(7.5,9.5) E23(8.5,9.5) E24(9.5,9.5) E25(10.5,9.5) E26(11.5,9.5) E27(12.5,9.5) E28(13.5,9.5) F1(-13.5,8.5) F2(-12.5,8.5) F3(-11.5,8.5) F4(-10.5,8.5) F5(-9.5,8.5) F6(-8.5,8.5) F7(-7.5,8.5) F8(-6.5,8.5) F9(-5.5,8.5) F10(-4.5,8.5) F11(-3.5,8.5) F12(-2.5,8.5) F13(-1.5,8.5) F14(-0.5,8.5) F15(0.5,8.5) F16(1.5,8.5) F17(2.5,8.5) F18(3.5,8.5) F19(4.5,8.5) F20(5.5,8.5) F21(6.5,8.5) F22(7.5,8.5) F23(8.5,8.5) F24(9.5,8.5) F25(10.5,8.5) F26(11.5,8.5) F27(12.5,8.5) F28(13.5,8.5) G1(-13.5,7.5) G2(-12.5,7.5) G3(-11.5,7.5) G4(-10.5,7.5) G5(-9.5,7.5) G6(-8.5,7.5) G7(-7.5,7.5) G8(-6.5,7.5) G9(-5.5,7.5) G10(-4.5,7.5) G11(-3.5,7.5) G12(-2.5,7.5) G13(-1.5,7.5) G14(-0.5,7.5) G15(0.5,7.5) G16(1.5,7.5) G17(2.5,7.5) G18(3.5,7.5) G19(4.5,7.5) G20(5.5,7.5) G21(6.5,7.5) G22(7.5,7.5) G23(8.5,7.5) G24(9.5,7.5) G25(10.5,7.5) G26(11.5,7.5) G27(12.5,7.5) G28(13.5,7.5) H1(-13.5,6.5) H2(-12.5,6.5) H3(-11.5,6.5) H4(-10.5,6.5) H5(-9.5,6.5) H6(-8.5,6.5) H7(-7.5,6.5) H8(-6.5,6.5) H9(-5.5,6.5) H10(-4.5,6.5) H11(-3.5,6.5) H12(-2.5,6.5) H13(-1.5,6.5) H14(-0.5,6.5) H15(0.5,6.5) H16(1.5,6.5) H17(2.5,6.5) H18(3.5,6.5) H19(4.5,6.5) H20(5.5,6.5) H21(6.5,6.5) H22(7.5,6.5) H23(8.5,6.5) H24(9.5,6.5) H25(10.5,6.5) H26(11.5,6.5) H27(12.5,6.5) H28(13.5,6.5) J1(-13.5,5.5) J2(-12.5,5.5) J3(-11.5,5.5) J4(-10.5,5.5) J5(-9.5,5.5) J6(-8.5,5.5) J7(-7.5,5.5) J8(-6.5,5.5) J9(-5.5,5.5) J10(-4.5,5.5) J11(-3.5,5.5) J12(-2.5,5.5) J13(-1.5,5.5) J14(-0.5,5.5) J15(0.5,5.5) J16(1.5,5.5) J17(2.5,5.5) J18(3.5,5.5) J19(4.5,5.5) J20(5.5,5.5) J21(6.5,5.5) J22(7.5,5.5) J23(8.5,5.5) J24(9.5,5.5) J25(10.5,5.5) J26(11.5,5.5) J27(12.5,5.5) J28(13.5,5.5) K1(-13.5,4.5) K2(-12.5,4.5) K3(-11.5,4.5) K4(-10.5,4.5) K5(-9.5,4.5) K6(-8.5,4.5) K7(-7.5,4.5) K8(-6.5,4.5) K9(-5.5,4.5) K10(-4.5,4.5) K11(-3.5,4.5) K12(-2.5,4.5) K13(-1.5,4.5) K14(-0.5,4.5) K15(0.5,4.5) K16(1.5,4.5) K17(2.5,4.5) K18(3.5,4.5) K19(4.5,4.5) K20(5.5,4.5) K21(6.5,4.5) K22(7.5,4.5) K23(8.5,4.5) K24(9.5,4.5) K25(10.5,4.5) K26(11.5,4.5) K27(12.5,4.5) K28(13.5,4.5) L1(-13.5,3.5) L2(-12.5,3.5) L3(-11.5,3.5) L4(-10.5,3.5) L5(-9.5,3.5) L6(-8.5,3.5) L7(-7.5,3.5) L8(-6.5,3.5) L9(-5.5,3.5) L10(-4.5,3.5) L11(-3.5,3.5) L12(-2.5,3.5) L13(-1.5,3.5) L14(-0.5,3.5) L15(0.5,3.5) L16(1.5,3.5) L17(2.5,3.5) L18(3.5,3.5) L19(4.5,3.5) L20(5.5,3.5) L21(6.5,3.5) L22(7.5,3.5) L23(8.5,3.5) L24(9.5,3.5) L25(10.5,3.5) L26(11.5,3.5) L27(12.5,3.5) L28(13.5,3.5) M1(-13.5,2.5) M2(-12.5,2.5) M3(-11.5,2.5) M4(-10.5,2.5) M5(-9.5,2.5) M6(-8.5,2.5) M7(-7.5,2.5) M8(-6.5,2.5) M9(-5.5,2.5) M10(-4.5,2.5) M11(-3.5,2.5) M12(-2.5,2.5) M13(-1.5,2.5) M14(-0.5,2.5) M15(0.5,2.5) M16(1.5,2.5) M17(2.5,2.5) M18(3.5,2.5) M19(4.5,2.5) M20(5.5,2.5) M21(6.5,2.5) M22(7.5,2.5) M23(8.5,2.5) M24(9.5,2.5) M25(10.5,2.5) M26(11.5,2.5) M27(12.5,2.5) M28(13.5,2.5) N1(-13.5,1.5) N2(-12.5,1.5) N3(-11.5,1.5) N4(-10.5,1.5) N5(-9.5,1.5) N6(-8.5,1.5) N7(-7.5,1.5) N8(-6.5,1.5) N9(-5.5,1.5) N10(-4.5,1.5) N11(-3.5,1.5) N12(-2.5,1.5) N13(-1.5,1.5) N14(-0.5,1.5) N15(0.5,1.5) N16(1.5,1.5) N17(2.5,1.5) N18(3.5,1.5) N19(4.5,1.5) N20(5.5,1.5) N21(6.5,1.5) N22(7.5,1.5) N23(8.5,1.5) N24(9.5,1.5) N25(10.5,1.5) N26(11.5,1.5) N27(12.5,1.5) N28(13.5,1.5) P1(-13.5,0.5) P2(-12.5,0.5) P3(-11.5,0.5) P4(-10.5,0.5) P5(-9.5,0.5) P6(-8.5,0.5) P7(-7.5,0.5) P8(-6.5,0.5) P9(-5.5,0.5) P10(-4.5,0.5) P11(-3.5,0.5) P12(-2.5,0.5) P13(-1.5,0.5) P14(-0.5,0.5) P15(0.5,0.5) P16(1.5,0.5) P17(2.5,0.5) P18(3.5,0.5) P19(4.5,0.5) P20(5.5,0.5) P21(6.5,0.5) P22(7.5,0.5) P23(8.5,0.5) P24(9.5,0.5) P25(10.5,0.5) P26(11.5,0.5) P27(12.5,0.5) P28(13.5,0.5) R1(-13.5,-0.5) R2(-12.5,-0.5) R3(-11.5,-0.5) R4(-10.5,-0.5) R5(-9.5,-0.5) R6(-8.5,-0.5) R7(-7.5,-0.5) R8(-6.5,-0.5) R9(-5.5,-0.5) R10(-4.5,-0.5) R11(-3.5,-0.5) R12(-2.5,-0.5) R13(-1.5,-0.5) R14(-0.5,-0.5) R15(0.5,-0.5) R16(1.5,-0.5) R17(2.5,-0.5) R18(3.5,-0.5) R19(4.5,-0.5) R20(5.5,-0.5) R21(6.5,-0.5) R22(7.5,-0.5) R23(8.5,-0.5) R24(9.5,-0.5) R25(10.5,-0.5) R26(11.5,-0.5) R27(12.5,-0.5) R28(13.5,-0.5) T1(-13.5,-1.5) T2(-12.5,-1.5) T3(-11.5,-1.5) T4(-10.5,-1.5) T5(-9.5,-1.5) T6(-8.5,-1.5) T7(-7.5,-1.5) T8(-6.5,-1.5) T9(-5.5,-1.5) T10(-4.5,-1.5) T11(-3.5,-1.5) T12(-2.5,-1.5) T13(-1.5,-1.5) T14(-0.5,-1.5) T15(0.5,-1.5) T16(1.5,-1.5) T17(2.5,-1.5) T18(3.5,-1.5) T19(4.5,-1.5) T20(5.5,-1.5) T21(6.5,-1.5) T22(7.5,-1.5) T23(8.5,-1.5) T24(9.5,-1.5) T25(10.5,-1.5) T26(11.5,-1.5) T27(12.5,-1.5) T28(13.5,-1.5) U1(-13.5,-2.5) U2(-12.5,-2.5) U3(-11.5,-2.5) U4(-10.5,-2.5) U5(-9.5,-2.5) U6(-8.5,-2.5) U7(-7.5,-2.5) U8(-6.5,-2.5) U9(-5.5,-2.5) U10(-4.5,-2.5) U11(-3.5,-2.5) U12(-2.5,-2.5) U13(-1.5,-2.5) U14(-0.5,-2.5) U15(0.5,-2.5) U16(1.5,-2.5) U17(2.5,-2.5) U18(3.5,-2.5) U19(4.5,-2.5) U20(5.5,-2.5) U21(6.5,-2.5) U22(7.5,-2.5) U23(8.5,-2.5) U24(9.5,-2.5) U25(10.5,-2.5) U26(11.5,-2.5) U27(12.5,-2.5) U28(13.5,-2.5) V1(-13.5,-3.5) V2(-12.5,-3.5) V3(-11.5,-3.5) V4(-10.5,-3.5) V5(-9.5,-3.5) V6(-8.5,-3.5) V7(-7.5,-3.5) V8(-6.5,-3.5) V9(-5.5,-3.5) V10(-4.5,-3.5) V11(-3.5,-3.5) V12(-2.5,-3.5) V13(-1.5,-3.5) V14(-0.5,-3.5) V15(0.5,-3.5) V16(1.5,-3.5) V17(2.5,-3.5) V18(3.5,-3.5) V19(4.5,-3.5) V20(5.5,-3.5) V21(6.5,-3.5) V22(7.5,-3.5) V23(8.5,-3.5) V24(9.5,-3.5) V25(10.5,-3.5) V26(11.5,-3.5) V27(12.5,-3.5) V28(13.5,-3.5) W1(-13.5,-4.5) W2(-12.5,-4.5) W3(-11.5,-4.5) W4(-10.5,-4.5) W5(-9.5,-4.5) W6(-8.5,-4.5) W7(-7.5,-4.5) W8(-6.5,-4.5) W9(-5.5,-4.5) W10(-4.5,-4.5) W11(-3.5,-4.5) W12(-2.5,-4.5) W13(-1.5,-4.5) W14(-0.5,-4.5) W15(0.5,-4.5) W16(1.5,-4.5) W17(2.5,-4.5) W18(3.5,-4.5) W19(4.5,-4.5) W20(5.5,-4.5) W21(6.5,-4.5) W22(7.5,-4.5) W23(8.5,-4.5) W24(9.5,-4.5) W25(10.5,-4.5) W26(11.5,-4.5) W27(12.5,-4.5) W28(13.5,-4.5) Y1(-13.5,-5.5) Y2(-12.5,-5.5) Y3(-11.5,-5.5) Y4(-10.5,-5.5) Y5(-9.5,-5.5) Y6(-8.5,-5.5) Y7(-7.5,-5.5) Y8(-6.5,-5.5) Y9(-5.5,-5.5) Y10(-4.5,-5.5) Y11(-3.5,-5.5) Y12(-2.5,-5.5) Y13(-1.5,-5.5) Y14(-0.5,-5.5) Y15(0.5,-5.5) Y16(1.5,-5.5) Y17(2.5,-5.5) Y18(3.5,-5.5) Y19(4.5,-5.5) Y20(5.5,-5.5) Y21(6.5,-5.5) Y22(7.5,-5.5) Y23(8.5,-5.5) Y24(9.5,-5.5) Y25(10.5,-5.5) Y26(11.5,-5.5) Y27(12.5,-5.5) Y28(13.5,-5.5)
  silkscreen extent -15.28,-14.5 14.5,14.5
MCCT-B [mm]
  rect 2x2.2 smd: 1(-1.5,0) 2(1.5,0)
  silkscreen extent -2.3,-1.6 1.8,1.6
QSOP16 [mm] "SSOP; 16 Leads; Body Width 3.9 mm; Pitch 0.635 mm"
  rect 0.4x2.2 smd: 1(-2.222,-2.6) 2(-1.587,-2.6) 3(-0.953,-2.6) 4(-0.318,-2.6) 5(0.318,-2.6) 6(0.953,-2.6) 7(1.587,-2.6) 8(2.222,-2.6) 9(2.222,2.6) 10(1.587,2.6) 11(0.953,2.6) 12(0.318,2.6) 13(-0.318,2.6) 14(-0.953,2.6) 15(-1.587,2.6) 16(-2.222,2.6)
  silkscreen extent -3.1,-2.72 2.5,1.1
"SMD _LED" [mm]
  rect 1.3x1.6 smd: 1(0.95,0) 2(-0.95,0)
  silkscreen extent -2.13,-1.15 2,1.15
SO-G5/P.95 [mm]
  rect 0.55x1.45 smd: 1(-0.95,-1.075) 2(0,-1.075) 3(0.95,-1.075) 4(0.95,1.075) 5(-0.95,1.075)
  silkscreen extent -2.42,-2.2 1.65,2.2
SO-G44/P.8 [mm]
  rect 0.45x1.45 smd: 1(-8.4,-5.575) 2(-7.6,-5.575) 3(-6.8,-5.575) 4(-6,-5.575) 5(-5.2,-5.575) 6(-4.4,-5.575) 7(-3.6,-5.575) 8(-2.8,-5.575) 9(-2,-5.575) 10(-1.2,-5.575) 11(-0.4,-5.575) 12(0.4,-5.575) 13(1.2,-5.575) 14(2,-5.575) 15(2.8,-5.575) 16(3.6,-5.575) 17(4.4,-5.575) 18(5.2,-5.575) 19(6,-5.575) 20(6.8,-5.575) 21(7.6,-5.575) 22(8.4,-5.575) 23(8.4,5.575) 24(7.6,5.575) 25(6.8,5.575) 26(6,5.575) 27(5.2,5.575) 28(4.4,5.575) 29(3.6,5.575) 30(2.8,5.575) 31(2,5.575) 32(1.2,5.575) 33(0.4,5.575) 34(-0.4,5.575) 35(-1.2,5.575) 36(-2,5.575) 37(-2.8,5.575) 38(-3.6,5.575) 39(-4.4,5.575) 40(-5.2,5.575) 41(-6,5.575) 42(-6.8,5.575) 43(-7.6,5.575) 44(-8.4,5.575)
  silkscreen extent -9.3,-5.7 9.25,4.45
TestPin [mil] "SingleTest Pin"
  round 60 hole 35: 1(0,0)

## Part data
C1 C2 C3 C4 C5 C6 C7 C8 C9 C10 C11 C12: library part CAP_POLAR, "Polar Capacitor"
C13 C14 C15 C16 C17 C18 C19 C20 C21 C22 C23 C24 C25 C26 C27 C28 C29 C30 C31 C32 C33 C34 C35 C36 C37 C38 C39 C40 C41 C42 C43 C44 C45 C46 C47 C48 C49 C50 C51 C52 C53 C54 C55: library part CAP, "Capacitor"
HDR1 HDR2: "Board-to-Board, Docking Station, 0.80mm (.031\") Pitch, Shielded Receptacle, Vertical, Ultra Low Profile, SMT"
L1 L2 L3 L4: library part Inductor, "Farnell part 323-7989"
LED1 LED2: library part HSMX-C670, "Typical RED GaAs SMD LED Agilent make"
R1 R2 R3 R4 R5 R6 R7 R8 R9 R10 R11 R12 R13 R14 R15: library part RES, "Resistor"
U1: "Stratix 1.5V FPGA, 426 I/Os, 780-Pin FineLine BGA, Speed Grade 7, Industrial Grade"
U2: library part SN74AHC1G04DBVR
U3 U4: "512Kx16Bit SRAM TSOP44"
U5: "SMBus Temperature Sensor with Internal and External Diode Input"

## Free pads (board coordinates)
  round 1 smd far side mask+1: FD2(4.3,56.9) FD3(51.1,50.9) FD4(62.9,27.4) FID1(17.5,24.9)
  round 1 smd mask+1: FD5(10.4,21) FD6(61.8,53.6)
  round 3.2 hole 3.5 unplated: LP(4,34) LP(65,4) LP(65,73)

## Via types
v1: diameter 0.6, hole 0.3, Top Layer to Bottom Layer, 560 vias

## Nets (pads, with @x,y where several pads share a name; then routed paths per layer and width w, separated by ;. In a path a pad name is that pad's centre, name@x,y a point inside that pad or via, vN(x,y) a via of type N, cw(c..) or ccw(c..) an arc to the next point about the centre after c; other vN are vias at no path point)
AUDIO_SPI_CSN: HDR1.11 U1.B25 | length 11.8
  Bottom Layer w0.2: HDR1.11@18.9,60.5 18.9,58.6 23.6,53.9 23.6,51.5 24.1,51 U1.B25@24.1,50.9
BLUE0: HDR1.14 U1.D23 | length 27.2
  Upper w0.2: v1(19.7,69.6) 19.7,66 20.5,65.2 20.5,59.2 24.3,55.5 24.3,49 24.9,48.4 v1(25.6,48.4)
  Bottom Layer w0.2: HDR1.14@19.7,67.2 v1(19.7,69.6) ; v1(25.6,48.4) U1.D23@26.1,48.9
BLUE1: HDR1.16 U1.C23 | length 26.9
  lower w0.2: v1(20.5,70.2) 20.5,66.1 21.3,65.2 21.3,59.1 24.9,55.8 24.9,49.6 25.1,49.4 v1(25.6,49.4)
  Bottom Layer w0.2: HDR1.16@20.5,67.3 v1(20.5,70.2) ; v1(25.6,49.4) U1.C23@26.1,49.9
BOC_CTS: HDR1.13 U1.A25 | length 10.2
  Bottom Layer w0.2: HDR1.13@19.7,60.4 19.7,58.6 24.1,54.2 ; U1.A25@24.1,51.9 24.1,54.1
BOC_RTS: HDR1.17 U1.A24 | length 10.2
  Bottom Layer w0.2: HDR1.17@21.3,60.5 21.3,58.4 25.1,54.7 U1.A24@25.1,51.9
BOC_RX: HDR1.19 U1.B23 | length 11.3
  Bottom Layer w0.2: HDR1.19@22.1,60.5 22.1,58.4 25.6,55.1 25.6,51.4 U1.B23@26.1,50.9
BOC_TX: HDR1.15 U1.B24 | length 11.5
  Bottom Layer w0.2: HDR1.15@20.5,60.5 20.5,58.5 24.6,54.4 24.6,52.5 24.6,51.4 U1.B24@25.1,50.9
BUZZER: HDR2.24 U1.AG23 | length 10.4
  Bottom Layer w0.2: HDR2.24@23.7,16.5 23.7,18 25.6,19.9 25.6,25.4 U1.AG23@26.1,25.9
CAN_RXD: HDR1.4 U1.J25 | length 36.7
  lower w0.2: v1(15.7,70.2) 15.7,65.9 16.5,65.1 16.5,59 20.6,54.9 20.6,47.3 21.3,46.6 25.2,46.6 25.6,46.2 v1(25.6,45.4)
  Bottom Layer w0.2: HDR1.4@15.7,67.3 v1(15.7,70.2) ; U1.J25@24.1,43.9 24.6,44.4 25.4,44.4 25.6,44.6 v1(25.6,45.4)
CAN_TXD: HDR1.2 U1.H25 | length 32.9
  lower w0.2: v1(14.9,69.5) 14.9,65.9 15.7,65.1 15.7,59.1 20.2,54.7 20.2,47.117 21.217,46.1 24.4,46.1 24.6,45.9 v1(24.6,45.4)
  Bottom Layer w0.2: HDR1.2@14.9,67.3 v1(14.9,69.5) ; U1.H25@24.1,44.9 v1(24.6,45.4)
FPGA_AUX0: HDR1.86 U1.C5 | length 24.6
  Upper w0.2: v1(45.6,50.4) 45.6,52.3 47.3,54.1 47.3,64.6 48.5,65.8 v1(48.5,69.7)
  Bottom Layer w0.2: U1.C5@44.1,49.9 44.6,50.4 v1(45.6,50.4) ; HDR1.86@48.5,67.3 v1(48.5,69.7)
FPGA_AUX1: HDR1.88 U1.C4 | length 26.3
  Upper w0.2: v1(45.6,49.4) 46.1,49.4 46.4,49.8 46.4,52.3 48.8,54.7 48.8,65.2 49.3,65.7 v1(49.3,70.3)
  Bottom Layer w0.2: U1.C4@45.1,49.9 v1(45.6,49.4) ; HDR1.88@49.3,67.4 v1(49.3,70.3)
FPGA_AUX2: HDR1.90 U1.J4 | length 34.3
  Upper w0.2: v1(43.6,45.4) 43.6,46.3 44.1,46.8 48.2,46.8 49.6,48.2 49.6,65 50.1,65.5 v1(50.1,69.7)
  Bottom Layer w0.2: v1(43.6,45.4) 43.6,44.6 43.8,44.4 44.6,44.4 U1.J4@45.1,43.9 ; HDR1.90@50.1,67.4 v1(50.1,69.7)
FPGA_AUX3: HDR1.92 U1.H4 | length 33.3
  Upper w0.2: v1(44.6,45.4) 44.6,45.9 44.9,46.2 48.5,46.2 50.1,47.8 50.1,50.1 50.1,64.8 50.9,65.6 v1(50.9,70.3)
  Bottom Layer w0.2: v1(44.6,45.4) U1.H4@45.1,44.9 ; HDR1.92@50.9,67.3 v1(50.9,70.3)
FPGA_CCLK: HDR1.66 R14.2 | length 6.5
  Top Layer w0.2: R14.2@39.25,72.5 v1(40.5,72.5)
  Bottom Layer w0.2: HDR1.66@40.5,67.3 v1(40.5,72.5)
FPGA_CCLK#: R14.1 U1.F16 | length 30.1
  Top Layer w0.2: v1(36.3,72.6) R14.1@37.5,72.6
  Upper w0.2: v1(32.6,51.4) 32,51.4 31.6,51.8 31.6,60.5 35.7,64.6 35.7,72.4 35.9,72.6 v1(36.3,72.6)
  Bottom Layer w0.2: v1(32.6,51.4) 32.6,47.4 U1.F16@33.1,46.9
FPGA_CLK: HDR2.2 U1.R27 | length 30
  Top Layer w0.2: v1(16.7,30.2) 17,29.9 19.5,29.9 20.3,30.8 20.3,37.1 20.8,37.6 21.8,37.6 v1(22.6,38.4)
  Bottom Layer w0.2: HDR2.2@14.9,16.5 14.9,17.7 14.9,21.1 12.9,23.1 12.9,26.3 v1(16.7,30.2) ; U1.R27@22.1,37.9 v1(22.6,38.4)
FPGA_CLK_1: HDR1.30 U1.P27 | length 38.7
  Top Layer w0.2: v1(21.6,38.4) 21.6,38.9 22.2,39.5 26,39.5 26.3,39.8 26.3,51.1 25.8,51.7 25.7,69.1 v1(26.1,69.6)
  Bottom Layer w0.2: v1(21.6,38.4) U1.P27@22.1,38.9 ; HDR1.30@26.1,67.3 v1(26.1,69.6)
FPGA_CLK_2: HDR1.32 U1.P25 | length 37.9
  Top Layer w0.2: v1(24.6,38.4) 24.6,39.1 26.4,39.1 26.9,39.6 26.9,51.1 26.3,51.8 26.3,68.6 26.9,69.2 v1(26.9,70.2)
  Bottom Layer w0.2: U1.P25@24.1,38.9 v1(24.6,38.4) ; HDR1.32@26.9,67.3 v1(26.9,70.2)
FPGA_DIN: HDR1.64 U1.H12 | length 28.5
  lower w0.2: v1(35.6,45.4) 36.129,45.4 36.3,45.571 36.3,60.9 39.7,64.3 v1(39.7,68.8)
  Bottom Layer w0.2: v1(35.6,45.4) 36.6,45.4 U1.H12@37.1,44.9 ; HDR1.64@39.7,67.4 v1(39.7,68.8)
FPGA_DONE: HDR1.74 R9.2 U1.G17 U2.2 | length 173.8
  Top Layer w0.2: U2.2@25.675,5 U2.2@25.775,5.1 ; U2.2@25.825,5 R9.2@29.75,5 ; 28,5 28,5.8 28.6,6.3 38.5,6.3 39.7,7.4 39.7,8.3 51.5,20.7 55.3,20.7 63.7,29.1 v1(64.8,29.1)
  lower w0.2: v1(31.6,46.4) 31.1,46.4 30.9,46.7 ; 39.7,70.6 39.7,73.9 41.2,75.5 53,75.5 56.1,72.4 56.1,60.4 66.5,50 66.5,29.5 66.1,29.1 v1(64.8,29.1) ; v1(43.7,68.9) 43.7,69.9 43,70.6 38.2,70.6 34.9,67.5 34.9,64.9 30.9,60.9 ; 30.9,46.7 30.9,60.9 ; 30.9,46.7 30.9,60.9
  Bottom Layer w0.2: v1(31.6,46.4) U1.G17@32.1,45.9 ; HDR1.74@43.7,67.4 v1(43.7,68.9)
FPGA_INIT: HDR1.68 R11.2 U1.M16 | length 39.9
  Top Layer w0.2: R11.2@41.3,65.25 v1(41.3,69.4)
  lower w0.2: v1(33.6,41.4) 33.6,42.1 32.8,42.9 32.8,49.9 33.6,50.8 33.6,60 37.3,63.9 37.3,67.6 39.3,69.4 v1(41.3,69.4)
  Bottom Layer w0.2: U1.M16@33.1,40.9 v1(33.6,41.4) ; HDR1.68@41.3,67.4 v1(41.3,69.4)
FPGA_M0: HDR1.60 U1.AC16 | length 110
  Top Layer w0.2: v1(33.6,30.4) 33.6,31.2 34.1,31.7 v1(57.1,31.7)
  Upper w0.2: v1(38.9,71.3) 38.9,73.1 41.2,75.5 53,75.5 56.1,72.4 56.1,60.4 66.5,50 66.5,29.5 65.5,28.4 61.2,28.4 58.9,31.7 v1(57.1,31.7)
  Bottom Layer w0.2: U1.AC16@33.1,29.9 v1(33.6,30.4) ; HDR1.60@38.1,67.2 38.1,70.8 38.5,71.3 v1(38.9,71.3)
FPGA_M1: HDR1.58 U1.W17 | length 114.7
  Top Layer w0.2: v1(37.6,30.4) 56.3,30.4 56.5,30.2 v1(57.8,30.2)
  lower w0.2: v1(37.3,71) 37.3,72.3 37.9,72.9 40.9,76 53.3,76 56.7,72.5 56.7,60.5 67.1,50.2 67,29.1 65.6,27.7 60.8,27.7 59,30.2 v1(57.8,30.2)
  Bottom Layer w0.2: U1.W17@32.1,33.9 32.6,33.4 33.347,33.4 33.6,33.147 33.6,31.623 33.823,31.4 37.338,31.4 37.6,31.138 v1(37.6,30.4) ; HDR1.58@37.3,67.4 v1(37.3,71)
FPGA_M2: HDR1.56 U1.AB15 | length 117
  Top Layer w0.2: v1(34.6,30.4) 34.6,30.9 34.8,31.1 56.3,31.1 56.5,30.9 v1(58.5,30.9)
  Upper w0.2: v1(36.5,70.2) 36.5,71.5 40.9,76 ; 37,72 40.9,76 ; v1(58.5,30.9) 60.8,27.7 65.6,27.7 67,29.1 67.1,50.2 56.7,60.5 56.7,72.5 53.3,76 40.9,76
  Bottom Layer w0.2: U1.AB15@34.1,30.9 v1(34.6,30.4) ; HDR1.56@36.5,67.4 v1(36.5,70.2)
FPGA_PROGRAM: HDR1.62 R10.2 U1.L16 | length 40.1
  Top Layer w0.2: R10.2@38.9,65.25 v1(38.9,69.9)
  lower w0.2: v1(32.6,41.4) 32.2,41.8 32.2,49.9 31.6,50.4 31.6,59.4 36.5,64.2 36.5,68 38.4,69.9 v1(38.9,69.9)
  Bottom Layer w0.2: v1(32.6,41.4) U1.L16@33.1,41.9 ; HDR1.62@38.9,67.5 v1(38.9,69.9)
FPGA_TCK: HDR1.72 TP7.1 U1.K12 | length 37.1
  Upper w0.2: v1(36.6,43.4) 36.9,43.8 36.9,60.6 42.9,66.6 v1(42.9,69.5)
  Bottom Layer w0.2: v1(36.6,43.4) U1.K12@37.1,42.9 ; HDR1.72@42.9,67.3 v1(42.9,69.5) 42.9,71.1 42.9,71.3 TP7.1@45.2,74.2
FPGA_TDI: HDR1.78 TP9.1 U1.G13 | length 39.5
  lower w0.2: v1(37.6,46.4) 39,46.4 39.6,47.1 39.6,61.1 45.3,66.7 v1(45.3,68.9)
  Bottom Layer w0.2: U1.G13@36.1,45.9 36.6,46.4 v1(37.6,46.4) ; TP9.1@50.2,73.2 47.1,73.2 45.3,71.1 v1(45.3,68.9) ; v1(45.3,68.9) HDR1.78@45.3,67.3 v1(45.3,68.9)
FPGA_TDO: HDR1.54 R2.1 TP8.1 | length 15.8
  Top Layer w0.2: TP8.1@35.7,73.9 35.7,74.8 36,75.1 R2.1@37.45,75.1
  Bottom Layer w0.2: HDR1.54@35.7,67.3 35.7,69.6 35.7,73.8 HDR1.54@35.7,67.3
FPGA_TDO#: R2.2 U1.H13 | length 36
  Top Layer w0.2: R2.2@39.35,75.1 40.4,75.1 41.2,74.3 v1(41.2,71.3) v1@41.3,71.2
  Upper w0.2: v1(35.6,44.4) 36.1,44.4 36.3,44.6 36.3,60.9 40.5,65.1 40.5,71.3 v1(41.2,71.3)
  Bottom Layer w0.2: v1(35.6,44.4) U1.H13@36.1,44.9
FPGA_TMS: HDR1.70 TP6.1 U1.F13 | length 32.8
  lower w0.2: v1(37.6,47.4) 36.9,48.1 36.9,60.6 42.1,65.8 v1(42.1,68.9)
  Bottom Layer w0.2: U1.F13@36,46.9 U1.F13@36.1,46.9 36.6,47.4 v1(37.6,47.4) ; HDR1.70@42.1,67.4 42.1,73.5 TP6.1@42.7,74.2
